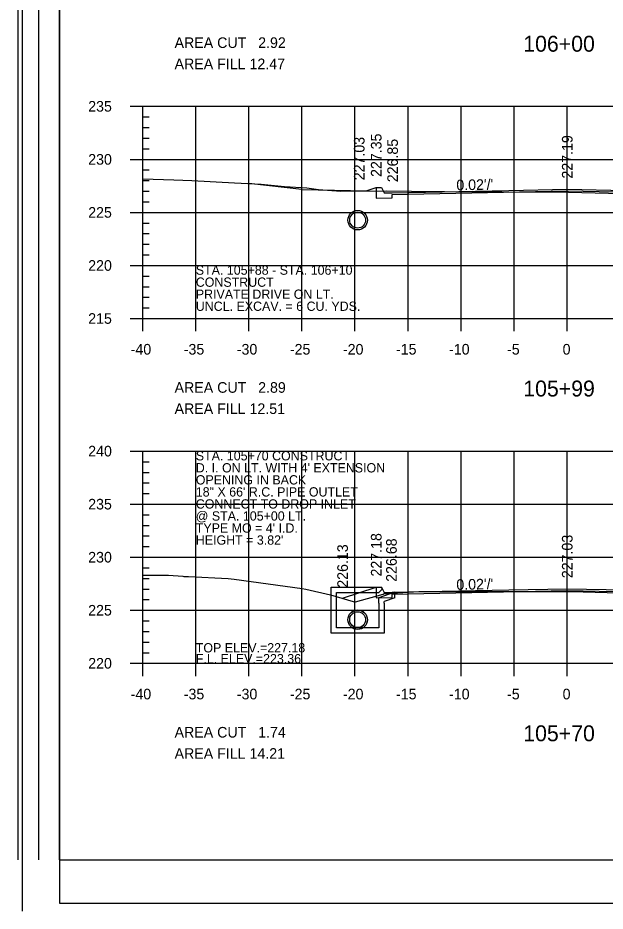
# Model space of a CAD drawing. Extents: x 1367903 to 1373764, y 376865 to 382130.
# Drawn here: x 1371165.1 to 1371275.8, y 377279.1 to 377447.5 of the extents above; entities that cross this region are included whole.
import ezdxf

# ---------------------------------------------------------------- set-up
doc = ezdxf.new("R2010")
doc.units = 0
for name, color, linetype in [('R_Axis', 7, 'Continuous'), ('R_Axis Annot', 7, 'Continuous'), ('R_Border', 7, 'Continuous'), ('R_Border PE', 7, 'Continuous'), ('R_Draft', 7, 'Continuous'), ('R_Drive', 7, 'Continuous'), ('R_Exist Surface', 7, 'Continuous'), ('R_Fin Surface', 7, 'Continuous'), ('R_Fin Surface Annot', 7, 'Continuous'), ('R_Grid', 7, 'Continuous'), ('R_Water', 7, 'Continuous'), ('R_Water Annot', 7, 'Continuous')]:
    doc.layers.add(name, color=color, linetype=linetype)

msp = doc.modelspace()

# ---------------------------------------------------------------- linework, layer by layer
for p, q in [((1371224.13, 377340.2), (1371233.63, 377340.2)), ((1371224.13, 377337.2), (1371224.13, 377340.2)), ((1371233.8, 377339.87), (1371233.63, 377340.2)), ((1371225.13, 377337.2), (1371225.13, 377339.2)), ((1371225.13, 377339.2), (1371233.13, 377339.2)), ((1371233.8, 377339.87), (1371233.13, 377339.2)), ((1371236.13, 377339.24), (1371233.13, 377338.2)), ((1371233.13, 377337.2), (1371233.13, 377338.2)), ((1371236.13, 377338.18), (1371234.13, 377337.49)), ((1371234.13, 377337.2), (1371234.13, 377337.49))]:
    msp.add_line(p, q)
for points in [[(1371232.63, 377415.53), (1371232.63, 377414.86), (1371232.63, 377414.86), (1371232.63, 377413.5), (1371235.63, 377413.56), (1371235.63, 377414.23), (1371268.63, 377414.89), (1371301.63, 377414.23), (1371301.63, 377413.56), (1371304.63, 377413.5), (1371304.63, 377414.94), (1371318.63, 377415.22), (1371318.63, 377415.81)], [(1371232.63, 377340.2), (1371232.63, 377339.53), (1371232.63, 377339.53), (1371232.63, 377338.17), (1371235.63, 377338.23), (1371235.63, 377338.9), (1371268.63, 377339.56), (1371301.63, 377338.9), (1371301.63, 377338.23), (1371304.63, 377338.17), (1371304.63, 377339.62), (1371318.63, 377339.9), (1371318.63, 377340.48)], [(1371236.13, 377338.18), (1371236.13, 377339.24)]]:
    msp.add_lwpolyline(points)
at = {"layer": 'R_Axis'}
for p, q in [((1371186.23, 377430.84), (1371191.03, 377430.84)), ((1371188.63, 377390.84), (1371188.63, 377430.84)), ((1371188.63, 377428.84), (1371189.83, 377428.84)), ((1371188.63, 377426.84), (1371189.83, 377426.84)), ((1371188.63, 377424.84), (1371189.83, 377424.84)), ((1371188.63, 377422.84), (1371189.83, 377422.84)), ((1371186.23, 377420.84), (1371191.03, 377420.84)), ((1371188.63, 377418.84), (1371189.83, 377418.84)), ((1371188.63, 377416.84), (1371189.83, 377416.84)), ((1371188.63, 377414.84), (1371189.83, 377414.84)), ((1371188.63, 377412.84), (1371189.83, 377412.84)), ((1371186.23, 377410.84), (1371191.03, 377410.84)), ((1371188.63, 377408.84), (1371189.83, 377408.84)), ((1371188.63, 377406.84), (1371189.83, 377406.84)), ((1371188.63, 377404.84), (1371189.83, 377404.84)), ((1371188.63, 377402.84), (1371189.83, 377402.84)), ((1371186.23, 377400.84), (1371191.03, 377400.84)), ((1371188.63, 377398.84), (1371189.83, 377398.84)), ((1371188.63, 377396.84), (1371189.83, 377396.84)), ((1371188.63, 377394.84), (1371189.83, 377394.84)), ((1371188.63, 377388.44), (1371188.63, 377393.24)), ((1371188.63, 377392.84), (1371189.83, 377392.84)), ((1371198.63, 377388.44), (1371198.63, 377393.24)), ((1371208.63, 377388.44), (1371208.63, 377393.24)), ((1371218.63, 377388.44), (1371218.63, 377393.24)), ((1371228.63, 377388.44), (1371228.63, 377393.24)), ((1371238.63, 377388.44), (1371238.63, 377393.24)), ((1371248.63, 377388.44), (1371248.63, 377393.24)), ((1371258.63, 377388.44), (1371258.63, 377393.24)), ((1371268.63, 377388.44), (1371268.63, 377393.24)), ((1371186.23, 377390.84), (1371191.03, 377390.84)), ((1371188.63, 377390.84), (1371348.63, 377390.84)), ((1371186.23, 377365.84), (1371191.03, 377365.84)), ((1371188.63, 377325.84), (1371188.63, 377365.84)), ((1371188.63, 377363.84), (1371189.83, 377363.84)), ((1371188.63, 377361.84), (1371189.83, 377361.84)), ((1371188.63, 377359.84), (1371189.83, 377359.84)), ((1371188.63, 377357.84), (1371189.83, 377357.84)), ((1371186.23, 377355.84), (1371191.03, 377355.84)), ((1371188.63, 377353.84), (1371189.83, 377353.84)), ((1371188.63, 377351.84), (1371189.83, 377351.84)), ((1371188.63, 377349.84), (1371189.83, 377349.84)), ((1371188.63, 377347.84), (1371189.83, 377347.84)), ((1371186.23, 377345.84), (1371191.03, 377345.84)), ((1371188.63, 377343.84), (1371189.83, 377343.84)), ((1371188.63, 377341.84), (1371189.83, 377341.84)), ((1371188.63, 377339.84), (1371189.83, 377339.84)), ((1371188.63, 377337.84), (1371189.83, 377337.84)), ((1371186.23, 377335.84), (1371191.03, 377335.84)), ((1371188.63, 377333.84), (1371189.83, 377333.84)), ((1371188.63, 377331.84), (1371189.83, 377331.84)), ((1371188.63, 377329.84), (1371189.83, 377329.84)), ((1371188.63, 377323.44), (1371188.63, 377328.24)), ((1371198.63, 377323.44), (1371198.63, 377328.24)), ((1371208.63, 377323.44), (1371208.63, 377328.24)), ((1371218.63, 377323.44), (1371218.63, 377328.24)), ((1371228.63, 377323.44), (1371228.63, 377328.24)), ((1371238.63, 377323.44), (1371238.63, 377328.24)), ((1371248.63, 377323.44), (1371248.63, 377328.24)), ((1371258.63, 377323.44), (1371258.63, 377328.24)), ((1371268.63, 377323.44), (1371268.63, 377328.24)), ((1371188.63, 377327.84), (1371189.83, 377327.84)), ((1371186.23, 377325.84), (1371191.03, 377325.84)), ((1371188.63, 377325.84), (1371348.63, 377325.84))]:
    msp.add_line(p, q, dxfattribs=at)
at = {"layer": 'R_Border'}
for p, q in [((1371165.9, 377620.35), (1371165.9, 377279.12)), ((1371172.93, 377611.47), (1371172.93, 377280.59)), ((1371172.93, 377280.59), (1371377.26, 377280.59))]:
    msp.add_line(p, q, dxfattribs=at)
at = {"layer": 'R_Border PE'}
for p, q in [((1371165.1, 377610.76), (1371165.1, 377288.8)), ((1371169.01, 377610.76), (1371169.01, 377288.8)), ((1371172.93, 377288.8), (1371172.93, 377603.25)), ((1371172.93, 377288.8), (1371377.26, 377288.8))]:
    msp.add_line(p, q, dxfattribs=at)
at = {"layer": 'R_Drive'}
for q in [(1371208.63, 377416.27), (1371233.96, 377414.87)]:
    msp.add_line((1371218.63, 377415.18), q, dxfattribs=at)
at = {"layer": 'R_Exist Surface'}
for points in [[(1371188.63, 377417.2), (1371194.52, 377416.97), (1371197.86, 377416.84), (1371205.94, 377416.41), (1371210.92, 377416.14), (1371215.33, 377415.72), (1371219.54, 377415.47), (1371221.76, 377415.19), (1371225.97, 377414.86), (1371234.48, 377414.93), (1371239.27, 377414.82), (1371251.7, 377414.74), (1371256.28, 377414.7), (1371268.89, 377414.67), (1371278.91, 377414.42)], [(1371188.63, 377342.46), (1371192.82, 377342.46), (1371193.51, 377342.46), (1371196.18, 377342.26), (1371196.39, 377342.22), (1371197.28, 377342.19), (1371204.74, 377341.81), (1371205.84, 377341.68), (1371218.69, 377339.97), (1371219.35, 377339.84), (1371224.03, 377338.74), (1371228.29, 377337.52), (1371228.7, 377337.43), (1371233.91, 377338.89), (1371234.12, 377338.97), (1371234.66, 377338.99), (1371240.68, 377339.37), (1371252.29, 377339.39), (1371269.39, 377339.37), (1371280.68, 377339.07)]]:
    msp.add_lwpolyline(points, dxfattribs=at)
at = {"layer": 'R_Fin Surface'}
for points in [[(1371230.73, 377414.9), (1371232.63, 377415.53), (1371233.63, 377415.53), (1371234.13, 377414.53), (1371235.63, 377414.56), (1371257.63, 377415), (1371268.63, 377415.22), (1371279.63, 377415), (1371301.63, 377414.56), (1371303.13, 377414.53), (1371303.63, 377415.53), (1371304.63, 377415.53), (1371308.63, 377415.61), (1371318.63, 377415.81), (1371326.21, 377413.28)], [(1371226.29, 377338.09), (1371232.63, 377340.2), (1371233.63, 377340.2), (1371234.13, 377339.2), (1371235.63, 377339.23), (1371257.63, 377339.67), (1371268.63, 377339.89), (1371279.63, 377339.67), (1371301.63, 377339.23), (1371303.13, 377339.2), (1371303.63, 377340.2), (1371304.63, 377340.2), (1371308.63, 377340.28), (1371318.63, 377340.48), (1371326.34, 377337.91)]]:
    msp.add_lwpolyline(points, dxfattribs=at)
at = {"layer": 'R_Grid'}
for p, q in [((1371188.63, 377430.84), (1371348.63, 377430.84)), ((1371188.63, 377390.84), (1371188.63, 377430.84)), ((1371198.63, 377390.84), (1371198.63, 377430.84)), ((1371208.63, 377390.84), (1371208.63, 377430.84)), ((1371218.63, 377390.84), (1371218.63, 377430.84)), ((1371228.63, 377390.84), (1371228.63, 377430.84)), ((1371238.63, 377390.84), (1371238.63, 377430.84)), ((1371248.63, 377390.84), (1371248.63, 377430.84)), ((1371258.63, 377390.84), (1371258.63, 377430.84)), ((1371268.63, 377390.84), (1371268.63, 377430.84)), ((1371188.63, 377420.84), (1371348.63, 377420.84)), ((1371188.63, 377410.84), (1371348.63, 377410.84)), ((1371188.63, 377400.84), (1371348.63, 377400.84)), ((1371188.63, 377390.84), (1371348.63, 377390.84)), ((1371188.63, 377365.84), (1371348.63, 377365.84)), ((1371188.63, 377325.84), (1371188.63, 377365.84)), ((1371198.63, 377325.84), (1371198.63, 377365.84)), ((1371208.63, 377325.84), (1371208.63, 377365.84)), ((1371218.63, 377325.84), (1371218.63, 377365.84)), ((1371228.63, 377325.84), (1371228.63, 377365.84)), ((1371238.63, 377325.84), (1371238.63, 377365.84)), ((1371248.63, 377325.84), (1371248.63, 377365.84)), ((1371258.63, 377325.84), (1371258.63, 377365.84)), ((1371268.63, 377325.84), (1371268.63, 377365.84)), ((1371188.63, 377355.84), (1371348.63, 377355.84)), ((1371188.63, 377345.84), (1371348.63, 377345.84)), ((1371188.63, 377335.84), (1371348.63, 377335.84)), ((1371188.63, 377325.84), (1371348.63, 377325.84))]:
    msp.add_line(p, q, dxfattribs=at)
at = {"layer": 'R_Water'}
for p, q in [((1371229.13, 377411.23), (1371229.13, 377411.19)), ((1371229.13, 377410.9), (1371229.13, 377410.85)), ((1371229.13, 377407.9), (1371229.13, 377407.85)), ((1371229.13, 377407.57), (1371229.13, 377407.52))]:
    msp.add_line(p, q, dxfattribs=at)
for points in [[(1371234.13, 377337.2), (1371234.13, 377331.55), (1371229.13, 377331.55), (1371224.13, 377331.55), (1371224.13, 377337.2)], [(1371233.13, 377337.2), (1371233.13, 377332.55), (1371229.13, 377332.55), (1371225.13, 377332.55), (1371225.13, 377337.2)]]:
    msp.add_lwpolyline(points, dxfattribs=at)
for centre, radius in [((1371229.13, 377409.38), 1.83), ((1371229.13, 377409.38), 1.5), ((1371229.13, 377334.06), 1.83), ((1371229.13, 377334.05), 1.83), ((1371229.13, 377334.06), 1.5), ((1371229.13, 377334.05), 1.5)]:
    msp.add_circle(centre, radius, dxfattribs=at)

# ---------------------------------------------------------------- texts
at = {"layer": 'R_Axis Annot'}
for s, height, p in [('AREA CUT   2.92', 2, (1371194.63, 377441.84)), ('106+00', 3, (1371260.34, 377441.14)), ('AREA FILL 12.47', 2, (1371194.63, 377437.84)), ('235', 2, (1371178.35, 377429.84)), ('230', 2, (1371178.35, 377419.84)), ('225', 2, (1371178.35, 377409.84)), ('220', 2, (1371178.35, 377399.84)), ('215', 2, (1371178.35, 377389.84)), ('-40', 2, (1371186.36, 377384.04)), ('-35', 2, (1371196.36, 377384.04)), ('-30', 2, (1371206.36, 377384.04)), ('-25', 2, (1371216.36, 377384.04)), ('-20', 2, (1371226.36, 377384.04)), ('-15', 2, (1371236.36, 377384.04)), ('-10', 2, (1371246.36, 377384.04)), ('-5', 2, (1371257.29, 377384.04)), ('0', 2, (1371267.76, 377384.04)), ('AREA CUT   2.89', 2, (1371194.63, 377376.84)), ('105+99', 3, (1371260.34, 377376.14)), ('AREA FILL 12.51', 2, (1371194.63, 377372.84)), ('240', 2, (1371178.35, 377364.84)), ('235', 2, (1371178.35, 377354.84)), ('230', 2, (1371178.35, 377344.84)), ('225', 2, (1371178.35, 377334.84)), ('220', 2, (1371178.35, 377324.84)), ('-40', 2, (1371186.36, 377319.04)), ('-35', 2, (1371196.36, 377319.04)), ('-30', 2, (1371206.36, 377319.04)), ('-25', 2, (1371216.36, 377319.04)), ('-20', 2, (1371226.36, 377319.04)), ('-15', 2, (1371236.36, 377319.04)), ('-10', 2, (1371246.36, 377319.04)), ('-5', 2, (1371257.29, 377319.04)), ('0', 2, (1371267.76, 377319.04)), ('AREA CUT   1.74', 2, (1371194.63, 377311.84)), ('105+70', 3, (1371260.34, 377311.14)), ('AREA FILL 14.21', 2, (1371194.63, 377307.84))]:
    msp.add_text(s, height=height, dxfattribs=at).set_placement(p)
at = {"layer": 'R_Draft'}
for s, p in [('STA. 105+88 - STA. 106+10', (1371198.63, 377399.09)), ('CONSTRUCT', (1371198.63, 377396.82)), ('PRIVATE DRIVE ON LT.', (1371198.63, 377394.55)), ('UNCL. EXCAV. = 6 CU. YDS.', (1371198.63, 377392.28)), ('STA. 105+70 CONSTRUCT', (1371198.63, 377364.09)), ("D. I. ON LT. WITH 4' EXTENSION", (1371198.63, 377361.82)), ('OPENING IN BACK', (1371198.63, 377359.55)), ('18" X 66\' R.C. PIPE OUTLET', (1371198.63, 377357.28)), ('CONNECT TO DROP INLET', (1371198.63, 377355.01)), ('@ STA. 105+00 LT.', (1371198.63, 377352.74)), ("TYPE MO = 4' I.D.", (1371198.63, 377350.47)), ("HEIGHT = 3.82'", (1371198.63, 377348.2))]:
    msp.add_text(s, height=1.75, dxfattribs=at).set_placement(p)
at = {"layer": 'R_Fin Surface Annot'}
for s, rotation, p in [('227.03', 90, (1371230.43, 377416.9)), ('227.35', 90, (1371233.63, 377417.53)), ('226.85', 90, (1371236.72, 377416.53)), ('227.19', 90, (1371269.63, 377417.22)), ("0.02'/'", 1.1458, (1371247.75, 377415)), ('227.18', 90, (1371233.63, 377342.2)), ('226.68', 90, (1371236.5, 377341.2)), ('227.03', 90, (1371269.63, 377341.89)), ('226.13', 90, (1371227.29, 377340.09)), ("0.02'/'", 1.1458, (1371247.75, 377339.67))]:
    msp.add_text(s, height=2, rotation=rotation, dxfattribs=at).set_placement(p)
at = {"layer": 'R_Water Annot'}
for s, p in [('TOP ELEV.=227.18', (1371198.63, 377327.89)), ('F.L. ELEV.=223.36', (1371198.63, 377325.84))]:
    msp.add_text(s, height=1.75, dxfattribs=at).set_placement(p)

doc.saveas('drawing.dxf')
